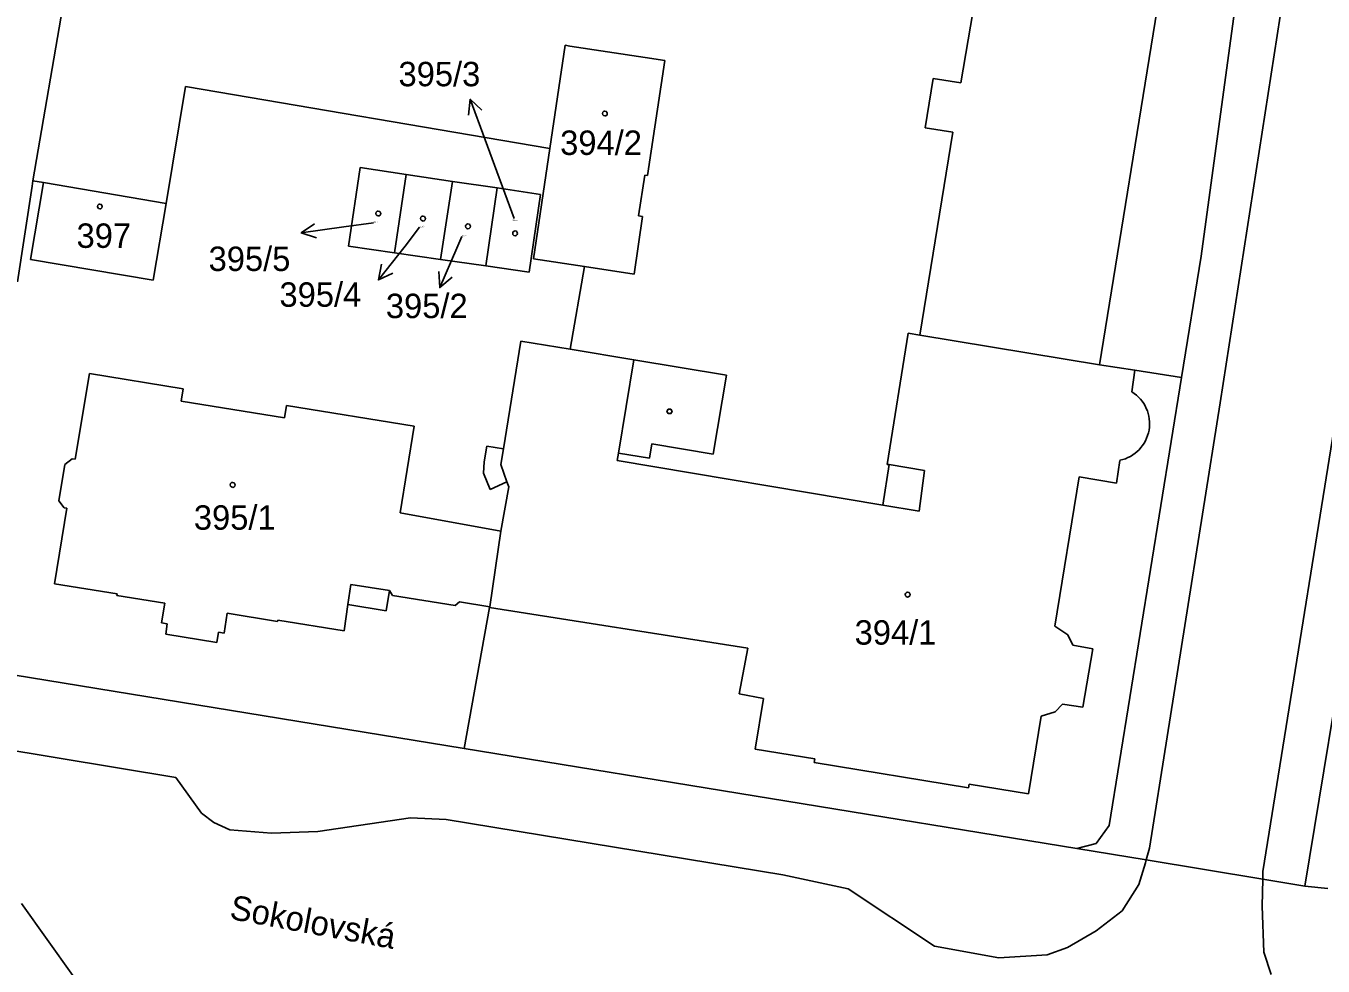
# Model space of a CAD drawing. Extents: x -851495 to -851222, y -1010479 to -1010202.
# Drawn here: x -851400.4 to -851310.2, y -1010428.3 to -1010362.9 of the extents above; entities that cross this region are included whole.
import ezdxf

# ---------------------------------------------------------------- set-up
doc = ezdxf.new("R2010")
doc.units = 0
for name, color, linetype in [('1', 7, 'Continuous'), ('12', 7, 'Continuous'), ('2', 7, 'Continuous'), ('4', 7, 'Continuous'), ('5', 7, 'Continuous'), ('7', 7, 'Continuous')]:
    doc.layers.add(name, color=color, linetype=linetype)

# ---------------------------------------------------------------- blocks, each defined once
blk = doc.blocks.new('10292')
blk.add_line((0, 3), (0, 0))
blk.add_lwpolyline([(-0.5, 2), (0, 3), (0.5, 2)])
blk = doc.blocks.new('402')
blk.add_lwpolyline([(0.09, 0.15), (0.18, 0), (0.09, -0.15), (-0.09, -0.15), (-0.18, 0), (-0.09, 0.15), (0.09, 0.15)])
blk = doc.blocks.new('404')
blk.add_lwpolyline([(0, 0.17), (0.1, 0.15), (0.15, 0.06), (0.17, 0), (0.15, -0.09), (0.07, -0.16), (0, -0.17), (-0.09, -0.14), (-0.15, -0.08), (-0.17, 0), (-0.15, 0.09), (-0.07, 0.16), (0, 0.17)])

msp = doc.modelspace()

# ---------------------------------------------------------------- linework, layer by layer
at = {"layer": '1'}
for p, q in [((-851399.92, -1010373.67), (-851396.37, -1010352.9)), ((-851333.35, -1010354.87), (-851335.38, -1010366.85)), ((-851318.65, -1010378.9), (-851315.46, -1010355.26)), ((-851362.91, -1010364.23), (-851363.97, -1010371.41)), ((-851362.57, -1010364.29), (-851362.91, -1010364.23)), ((-851357.34, -1010365.08), (-851362.57, -1010364.29)), ((-851355.96, -1010365.29), (-851357.34, -1010365.08)), ((-851357.17, -1010373.29), (-851355.96, -1010365.29)), ((-851337.3, -1010366.54), (-851337.85, -1010369.97)), ((-851335.38, -1010366.85), (-851337.3, -1010366.54)), ((-851390.65, -1010375.23), (-851389.3, -1010367.1)), ((-851389.3, -1010367.1), (-851363.97, -1010371.41)), ((-851335.94, -1010370.28), (-851338.24, -1010384.4)), ((-851337.85, -1010369.97), (-851335.94, -1010370.28)), ((-851363.97, -1010371.41), (-851365.1, -1010379.09)), ((-851377.16, -1010372.74), (-851377.98, -1010378.2)), ((-851373.95, -1010373.22), (-851377.16, -1010372.74)), ((-851399.19, -1010373.79), (-851400.09, -1010379.13)), ((-851399.98, -1010374.03), (-851399.92, -1010373.67)), ((-851399.92, -1010373.67), (-851399.19, -1010373.79)), ((-851390.65, -1010375.23), (-851399.19, -1010373.79)), ((-851374.77, -1010378.68), (-851373.95, -1010373.22)), ((-851370.73, -1010373.7), (-851373.95, -1010373.22)), ((-851370.73, -1010373.7), (-851371.57, -1010379.15)), ((-851370.73, -1010373.7), (-851367.63, -1010374.16)), ((-851357.35, -1010373.26), (-851357.81, -1010376.09)), ((-851357.35, -1010373.26), (-851357.17, -1010373.29)), ((-851399.98, -1010374.03), (-851401, -1010380.7)), ((-851367.63, -1010374.16), (-851368.42, -1010379.58)), ((-851367.63, -1010374.16), (-851364.61, -1010374.61)), ((-851364.61, -1010374.61), (-851365.4, -1010380.03)), ((-851391.55, -1010380.57), (-851390.65, -1010375.23)), ((-851358.09, -1010380.15), (-851357.52, -1010376.14)), ((-851357.52, -1010376.14), (-851357.81, -1010376.09)), ((-851377.98, -1010378.2), (-851374.77, -1010378.68)), ((-851400.09, -1010379.13), (-851391.55, -1010380.57)), ((-851371.57, -1010379.15), (-851374.77, -1010378.68)), ((-851368.42, -1010379.58), (-851371.57, -1010379.15)), ((-851365.1, -1010379.09), (-851361.55, -1010379.63)), ((-851320.02, -1010387.35), (-851318.65, -1010378.9)), ((-851365.4, -1010380.03), (-851368.42, -1010379.58)), ((-851361.55, -1010379.63), (-851362.55, -1010385.39)), ((-851361.55, -1010379.63), (-851358.09, -1010380.15)), ((-851338.24, -1010384.4), (-851325.73, -1010386.47)), ((-851365.99, -1010384.82), (-851367.2, -1010392.32)), ((-851365.99, -1010384.82), (-851362.55, -1010385.39)), ((-851325.73, -1010386.47), (-851323.27, -1010386.85)), ((-851320.02, -1010387.35), (-851325.06, -1010418.54)), ((-851323.27, -1010386.85), (-851320.02, -1010387.35)), ((-851368.36, -1010392.14), (-851368.54, -1010393.22)), ((-851367.2, -1010392.32), (-851368.36, -1010392.14)), ((-851368.54, -1010393.22), (-851368.59, -1010394.01)), ((-851368.59, -1010394.01), (-851368.12, -1010395.15)), ((-851368.12, -1010395.15), (-851366.95, -1010394.61)), ((-851366.95, -1010394.61), (-851366.82, -1010394.97)), ((-851367.37, -1010398.04), (-851366.82, -1010394.97)), ((-851367.37, -1010398.04), (-851368.15, -1010403.31)), ((-851368.16, -1010403.36), (-851369.92, -1010413.18)), ((-851368.15, -1010403.31), (-851368.16, -1010403.36)), ((-851369.92, -1010413.18), (-851403.77, -1010407.65)), ((-851389.99, -1010415.2), (-851404.51, -1010412.78)), ((-851327.32, -1010420.13), (-851369.92, -1010413.18)), ((-851388.19, -1010417.69), (-851389.99, -1010415.2)), ((-851387.35, -1010418.33), (-851388.19, -1010417.69)), ((-851373.65, -1010418), (-851380.11, -1010418.95)), ((-851371.17, -1010418.12), (-851373.65, -1010418)), ((-851347.75, -1010421.98), (-851371.17, -1010418.12)), ((-851386.22, -1010418.85), (-851387.35, -1010418.33)), ((-851383.32, -1010419.08), (-851386.22, -1010418.85)), ((-851380.11, -1010418.95), (-851383.32, -1010419.08)), ((-851325.97, -1010419.79), (-851325.06, -1010418.54)), ((-851327.32, -1010420.13), (-851325.97, -1010419.79)), ((-851327.32, -1010420.13), (-851322.48, -1010420.93)), ((-851323, -1010422.64), (-851322.53, -1010421.14)), ((-851322.53, -1010421.14), (-851322.48, -1010420.93)), ((-851322.48, -1010420.93), (-851314.38, -1010422.27)), ((-851343.22, -1010422.95), (-851347.75, -1010421.98)), ((-851323, -1010422.64), (-851324.16, -1010424.47)), ((-851314.42, -1010424.16), (-851314.38, -1010422.27)), ((-851314.38, -1010422.27), (-851311.44, -1010422.76)), ((-851337.21, -1010426.95), (-851343.22, -1010422.95)), ((-851309.84, -1010422.92), (-851311.44, -1010422.76)), ((-851400.73, -1010423.98), (-851397.15, -1010428.97)), ((-851324.16, -1010424.47), (-851325.97, -1010425.87)), ((-851314.31, -1010427.36), (-851314.42, -1010424.16)), ((-851325.97, -1010425.87), (-851327.95, -1010427.03)), ((-851332.74, -1010427.75), (-851337.21, -1010426.95)), ((-851327.95, -1010427.03), (-851329.38, -1010427.54)), ((-851329.38, -1010427.54), (-851332.74, -1010427.75)), ((-851313.8, -1010428.9), (-851314.31, -1010427.36))]:
    msp.add_line(p, q, dxfattribs=at)
at = {"layer": '12'}
for p, q in [((-851318.6, -1010342.35), (-851325.73, -1010386.47)), ((-851333.35, -1010354.87), (-851335.38, -1010366.85)), ((-851362.91, -1010364.23), (-851363.97, -1010371.41)), ((-851362.57, -1010364.29), (-851362.91, -1010364.23)), ((-851357.34, -1010365.08), (-851362.57, -1010364.29)), ((-851355.96, -1010365.29), (-851357.34, -1010365.08)), ((-851357.17, -1010373.29), (-851355.96, -1010365.29)), ((-851337.3, -1010366.54), (-851337.85, -1010369.97)), ((-851335.38, -1010366.85), (-851337.3, -1010366.54)), ((-851335.94, -1010370.28), (-851338.24, -1010384.4)), ((-851337.85, -1010369.97), (-851335.94, -1010370.28)), ((-851363.97, -1010371.41), (-851365.1, -1010379.09)), ((-851377.16, -1010372.74), (-851377.98, -1010378.2)), ((-851373.95, -1010373.22), (-851377.16, -1010372.74)), ((-851399.19, -1010373.79), (-851400.09, -1010379.13)), ((-851390.65, -1010375.23), (-851399.19, -1010373.79)), ((-851374.77, -1010378.68), (-851373.95, -1010373.22)), ((-851374.77, -1010378.68), (-851373.95, -1010373.22)), ((-851370.73, -1010373.7), (-851373.95, -1010373.22)), ((-851370.73, -1010373.7), (-851371.57, -1010379.15)), ((-851370.73, -1010373.7), (-851371.57, -1010379.15)), ((-851370.73, -1010373.7), (-851367.63, -1010374.16)), ((-851357.35, -1010373.26), (-851357.81, -1010376.09)), ((-851357.35, -1010373.26), (-851357.17, -1010373.29)), ((-851367.63, -1010374.16), (-851368.42, -1010379.58)), ((-851367.63, -1010374.16), (-851368.42, -1010379.58)), ((-851367.63, -1010374.16), (-851364.61, -1010374.61)), ((-851364.61, -1010374.61), (-851365.4, -1010380.03)), ((-851391.55, -1010380.57), (-851390.65, -1010375.23)), ((-851358.09, -1010380.15), (-851357.52, -1010376.14)), ((-851357.52, -1010376.14), (-851357.81, -1010376.09)), ((-851377.98, -1010378.2), (-851374.77, -1010378.68)), ((-851400.09, -1010379.13), (-851391.55, -1010380.57)), ((-851371.57, -1010379.15), (-851374.77, -1010378.68)), ((-851368.42, -1010379.58), (-851371.57, -1010379.15)), ((-851365.1, -1010379.09), (-851361.55, -1010379.63)), ((-851365.4, -1010380.03), (-851368.42, -1010379.58)), ((-851361.55, -1010379.63), (-851358.09, -1010380.15)), ((-851339.05, -1010384.27), (-851340.51, -1010393.4)), ((-851338.24, -1010384.4), (-851339.05, -1010384.27)), ((-851338.24, -1010384.4), (-851325.73, -1010386.47)), ((-851338.24, -1010384.4), (-851325.73, -1010386.47)), ((-851365.99, -1010384.82), (-851367.2, -1010392.32)), ((-851365.99, -1010384.82), (-851362.55, -1010385.39)), ((-851362.55, -1010385.39), (-851358.12, -1010386.12)), ((-851359.19, -1010392.62), (-851358.12, -1010386.12)), ((-851325.73, -1010386.47), (-851323.27, -1010386.85)), ((-851396.99, -1010393.05), (-851396, -1010387.08)), ((-851389.47, -1010388.14), (-851396, -1010387.08)), ((-851323.27, -1010386.85), (-851323.48, -1010388.36)), ((-851389.61, -1010389), (-851389.47, -1010388.14)), ((-851382.43, -1010390.16), (-851389.61, -1010389)), ((-851382.29, -1010389.3), (-851382.43, -1010390.16)), ((-851373.4, -1010390.74), (-851382.29, -1010389.3)), ((-851373.4, -1010390.74), (-851374.39, -1010396.77)), ((-851367.2, -1010392.32), (-851367.37, -1010393.41)), ((-851359.19, -1010392.62), (-851359.28, -1010393.14)), ((-851398.12, -1010395.93), (-851397.7, -1010393.41)), ((-851397.7, -1010393.41), (-851397.2, -1010393.01)), ((-851397.2, -1010393.01), (-851396.99, -1010393.05)), ((-851366.95, -1010394.61), (-851367.37, -1010393.41)), ((-851359.28, -1010393.14), (-851340.8, -1010396.24)), ((-851340.36, -1010393.42), (-851340.51, -1010393.4)), ((-851337.91, -1010393.82), (-851340.36, -1010393.42)), ((-851324.31, -1010393.12), (-851324.55, -1010394.72)), ((-851366.95, -1010394.61), (-851366.82, -1010394.97)), ((-851338.28, -1010396.66), (-851337.91, -1010393.82)), ((-851327.14, -1010394.26), (-851328.83, -1010404.66)), ((-851324.55, -1010394.72), (-851327.14, -1010394.26)), ((-851367.37, -1010398.04), (-851366.82, -1010394.97)), ((-851398.43, -1010401.71), (-851397.56, -1010396.45)), ((-851397.75, -1010396.42), (-851398.12, -1010395.93)), ((-851397.56, -1010396.45), (-851397.75, -1010396.42)), ((-851340.8, -1010396.24), (-851338.28, -1010396.66)), ((-851374.39, -1010396.77), (-851367.37, -1010398.04)), ((-851367.37, -1010398.04), (-851368.15, -1010403.31)), ((-851367.37, -1010398.04), (-851368.15, -1010403.31)), ((-851398.43, -1010401.71), (-851394.07, -1010402.42)), ((-851377.8, -1010401.76), (-851378.03, -1010403.16)), ((-851377.8, -1010401.76), (-851375.12, -1010402.19)), ((-851394.07, -1010402.42), (-851394.08, -1010402.52)), ((-851394.08, -1010402.52), (-851390.75, -1010403.06)), ((-851375.12, -1010402.19), (-851374.92, -1010402.53)), ((-851374.92, -1010402.53), (-851370.55, -1010403.23)), ((-851390.75, -1010403.06), (-851390.97, -1010404.44)), ((-851378.03, -1010403.16), (-851378.28, -1010404.99)), ((-851370.55, -1010403.23), (-851370.26, -1010402.97)), ((-851370.26, -1010402.97), (-851368.15, -1010403.31)), ((-851368.15, -1010403.31), (-851368.16, -1010403.36)), ((-851368.16, -1010403.36), (-851350.19, -1010406.2)), ((-851390.97, -1010404.44), (-851390.58, -1010404.5)), ((-851390.58, -1010404.5), (-851390.69, -1010405.22)), ((-851386.63, -1010405.15), (-851386.41, -1010403.77)), ((-851386.41, -1010403.77), (-851382.9, -1010404.34)), ((-851382.9, -1010404.34), (-851382.89, -1010404.24)), ((-851382.89, -1010404.24), (-851378.28, -1010404.99)), ((-851390.69, -1010405.22), (-851387.14, -1010405.81)), ((-851387.14, -1010405.81), (-851387.02, -1010405.09)), ((-851387.02, -1010405.09), (-851386.63, -1010405.15)), ((-851327.94, -1010405.26), (-851328.83, -1010404.66)), ((-851327.59, -1010405.99), (-851327.94, -1010405.26)), ((-851350.19, -1010406.2), (-851350.79, -1010409.37)), ((-851326.19, -1010406.23), (-851327.59, -1010405.99)), ((-851326.88, -1010410.31), (-851326.19, -1010406.23)), ((-851349.11, -1010409.69), (-851350.79, -1010409.37)), ((-851349.69, -1010413.23), (-851349.11, -1010409.69)), ((-851330.67, -1010416.34), (-851329.79, -1010410.93)), ((-851329.79, -1010410.93), (-851328.81, -1010410.63)), ((-851328.81, -1010410.63), (-851328.3, -1010410.1)), ((-851328.3, -1010410.1), (-851326.88, -1010410.31)), ((-851345.54, -1010413.91), (-851349.69, -1010413.23)), ((-851345.58, -1010414.15), (-851345.54, -1010413.91)), ((-851334.84, -1010415.91), (-851345.58, -1010414.15)), ((-851334.8, -1010415.67), (-851334.84, -1010415.91)), ((-851330.67, -1010416.34), (-851334.8, -1010415.67))]:
    msp.add_line(p, q, dxfattribs=at)
msp.add_arc((-851324.85, -1010390.57), 2.603, 281.95151, 58.26609, dxfattribs=at)
at = {"layer": '4'}
for p, q in [((-851318.6, -1010342.35), (-851325.73, -1010386.47)), ((-851310.67, -1010345.99), (-851317.33, -1010389.12)), ((-851303.11, -1010371.88), (-851311.44, -1010422.76)), ((-851306.95, -1010375.51), (-851314.37, -1010421.74)), ((-851339.05, -1010384.27), (-851340.51, -1010393.4)), ((-851338.24, -1010384.4), (-851339.05, -1010384.27)), ((-851362.55, -1010385.39), (-851358.12, -1010386.12)), ((-851359.19, -1010392.62), (-851358.12, -1010386.12)), ((-851351.69, -1010387.18), (-851358.12, -1010386.12)), ((-851396.99, -1010393.05), (-851396, -1010387.08)), ((-851389.47, -1010388.14), (-851396, -1010387.08)), ((-851352.6, -1010392.69), (-851351.69, -1010387.18)), ((-851323.27, -1010386.85), (-851323.48, -1010388.36)), ((-851389.61, -1010389), (-851389.47, -1010388.14)), ((-851382.43, -1010390.16), (-851389.61, -1010389)), ((-851317.33, -1010389.12), (-851322.26, -1010420.11)), ((-851382.29, -1010389.3), (-851382.43, -1010390.16)), ((-851373.4, -1010390.74), (-851382.29, -1010389.3)), ((-851373.4, -1010390.74), (-851374.39, -1010396.77)), ((-851356.88, -1010391.97), (-851357.04, -1010392.97)), ((-851352.6, -1010392.69), (-851356.88, -1010391.97)), ((-851367.2, -1010392.32), (-851367.37, -1010393.41)), ((-851359.19, -1010392.62), (-851359.28, -1010393.14)), ((-851357.04, -1010392.97), (-851359.19, -1010392.62)), ((-851398.12, -1010395.93), (-851397.7, -1010393.41)), ((-851397.7, -1010393.41), (-851397.2, -1010393.01)), ((-851397.2, -1010393.01), (-851396.99, -1010393.05)), ((-851366.95, -1010394.61), (-851367.37, -1010393.41)), ((-851359.28, -1010393.14), (-851340.8, -1010396.24)), ((-851340.36, -1010393.42), (-851340.8, -1010396.24)), ((-851340.36, -1010393.42), (-851340.51, -1010393.4)), ((-851337.91, -1010393.82), (-851340.36, -1010393.42)), ((-851324.31, -1010393.12), (-851324.55, -1010394.72)), ((-851338.28, -1010396.66), (-851337.91, -1010393.82)), ((-851327.14, -1010394.26), (-851328.83, -1010404.66)), ((-851324.55, -1010394.72), (-851327.14, -1010394.26)), ((-851398.43, -1010401.71), (-851397.56, -1010396.45)), ((-851397.75, -1010396.42), (-851398.12, -1010395.93)), ((-851397.56, -1010396.45), (-851397.75, -1010396.42)), ((-851340.8, -1010396.24), (-851338.28, -1010396.66)), ((-851374.39, -1010396.77), (-851367.37, -1010398.04)), ((-851398.43, -1010401.71), (-851394.07, -1010402.42)), ((-851377.8, -1010401.76), (-851378.03, -1010403.16)), ((-851377.8, -1010401.76), (-851375.12, -1010402.19)), ((-851394.07, -1010402.42), (-851394.08, -1010402.52)), ((-851394.08, -1010402.52), (-851390.75, -1010403.06)), ((-851375.12, -1010402.19), (-851375.35, -1010403.59)), ((-851375.12, -1010402.19), (-851374.92, -1010402.53)), ((-851374.92, -1010402.53), (-851370.55, -1010403.23)), ((-851390.75, -1010403.06), (-851390.97, -1010404.44)), ((-851378.03, -1010403.16), (-851378.28, -1010404.99)), ((-851375.35, -1010403.59), (-851378.03, -1010403.16)), ((-851370.55, -1010403.23), (-851370.26, -1010402.97)), ((-851370.26, -1010402.97), (-851368.15, -1010403.31)), ((-851368.16, -1010403.36), (-851350.19, -1010406.2)), ((-851390.97, -1010404.44), (-851390.58, -1010404.5)), ((-851390.58, -1010404.5), (-851390.69, -1010405.22)), ((-851386.63, -1010405.15), (-851386.41, -1010403.77)), ((-851386.41, -1010403.77), (-851382.9, -1010404.34)), ((-851382.9, -1010404.34), (-851382.89, -1010404.24)), ((-851382.89, -1010404.24), (-851378.28, -1010404.99)), ((-851390.69, -1010405.22), (-851387.14, -1010405.81)), ((-851387.14, -1010405.81), (-851387.02, -1010405.09)), ((-851387.02, -1010405.09), (-851386.63, -1010405.15)), ((-851327.94, -1010405.26), (-851328.83, -1010404.66)), ((-851327.59, -1010405.99), (-851327.94, -1010405.26)), ((-851350.19, -1010406.2), (-851350.79, -1010409.37)), ((-851326.19, -1010406.23), (-851327.59, -1010405.99)), ((-851326.88, -1010410.31), (-851326.19, -1010406.23)), ((-851349.11, -1010409.69), (-851350.79, -1010409.37)), ((-851349.69, -1010413.23), (-851349.11, -1010409.69)), ((-851330.67, -1010416.34), (-851329.79, -1010410.93)), ((-851329.79, -1010410.93), (-851328.81, -1010410.63)), ((-851328.81, -1010410.63), (-851328.3, -1010410.1)), ((-851328.3, -1010410.1), (-851326.88, -1010410.31)), ((-851345.54, -1010413.91), (-851349.69, -1010413.23)), ((-851345.58, -1010414.15), (-851345.54, -1010413.91)), ((-851334.84, -1010415.91), (-851345.58, -1010414.15)), ((-851334.8, -1010415.67), (-851334.84, -1010415.91)), ((-851330.67, -1010416.34), (-851334.8, -1010415.67)), ((-851322.26, -1010420.11), (-851322.48, -1010420.93)), ((-851314.37, -1010421.74), (-851314.38, -1010422.27))]:
    msp.add_line(p, q, dxfattribs=at)
msp.add_arc((-851324.85, -1010390.57), 2.603, 281.95151, 58.26609, dxfattribs=at)
at = {"layer": '7'}
for p, q in [((-851366.45, -1010376.29), (-851368.47, -1010370.8)), ((-851376.24, -1010376.58), (-851378.29, -1010376.87)), ((-851373.03, -1010376.9), (-851374.04, -1010378.2)), ((-851370.09, -1010377.53), (-851370.44, -1010378.34))]:
    msp.add_line(p, q, dxfattribs=at)

# ---------------------------------------------------------------- block references
at = {"layer": '5'}
for name, p in [('404', (-851360.14, -1010368.98)), ('404', (-851395.27, -1010375.45)), ('404', (-851375.9, -1010375.94)), ('404', (-851372.79, -1010376.29)), ('404', (-851369.66, -1010376.83)), ('404', (-851366.38, -1010377.32)), ('402', (-851355.64, -1010389.71)), ('404', (-851386.03, -1010394.83)), ('404', (-851339.08, -1010402.47))]:
    msp.add_blockref(name, p, dxfattribs=at)
at = {"layer": '7'}
for p, rotation in [((-851368.47, -1010370.8), 20.22541), ((-851378.29, -1010376.87), 97.918487), ((-851374.04, -1010378.2), 141.978942), ((-851370.44, -1010378.34), 156.818549)]:
    msp.add_blockref('10292', p, dxfattribs=dict(at, rotation=rotation))

# ---------------------------------------------------------------- texts
at = {"layer": '2'}
for s, height, p in [('394/2', 1.7, (-851363.25, -1010371.86)), ('397', 1.7, (-851396.89, -1010378.33)), ('395/5', 0.1, (-851376.23, -1010376.58)), ('395/3', 0.1, (-851366.56, -1010376.46)), ('395/4', 0.1, (-851373.02, -1010376.9)), ('395/2', 0.1, (-851370.08, -1010377.53)), ('395/1', 1.7, (-851388.73, -1010397.95)), ('394/1', 1.7, (-851342.766, -1010405.95))]:
    msp.add_text(s, height=height, dxfattribs=at).set_placement(p)
at = {"layer": '7'}
for s, p in [('395/3', (-851374.494, -1010367.08)), ('395/5', (-851387.704, -1010379.94)), ('395/4', (-851382.775, -1010382.43)), ('395/2', (-851375.374, -1010383.22))]:
    msp.add_text(s, height=1.7, dxfattribs=at).set_placement(p)
msp.add_text('Sokolovská', height=1.7, rotation=349.562, dxfattribs=at).set_placement((-851386.31, -1010425.03))

doc.saveas('drawing.dxf')
